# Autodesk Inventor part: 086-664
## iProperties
Author: CM
Shininess: 28.0
Angle Display Precision: 2
Document Length Units: 11272
Document Angle Units: 11286
Document Time Units: 11279
Document Mass Units: 11290
Document Length Units Precision: 3
Document Angle Units Precision: 2
Compacted: True
PropertySet Name: _Private Model Information
Created: 2002-03
Part Number: 086-664
Material: Nylon-6/6 (Black)
Description: SPA-NAUR P-CLIP, WHITE
Document SubType Name: Modeling
Designer: CM
Control State: 0
Master: False
Checked Out: False
PropertySet Name: Design Tracking Control
Density: 1.13
Volumn: 0.6059527942757658
Area: 9.682796208592487
PropertySet Name: Model Information
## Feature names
1. Extrusion2
2. Hole1
3. Extrusion3
4. Fillet1
